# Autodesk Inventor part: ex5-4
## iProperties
Created: 2002-01
Part Number: ex5-4
Document SubType Name: Modeling
Designer: Elise Moss
Density: 1 g/cm^3
Mass: 106.964 g
Surface Area: 328.191 cm^2
Volume: 106.964 cm^3
d0: 4.650 in
d1: 2.325 in
d2: 4.650 in
d3: 2.325 in
d4: 0.200 in
d32: 0.850 in
d33: 0.850 in
d34: 0.168 in
d36: 0.300 in
d37: 0.195 in
d41: 0.030 in
d5: 0.310 in
d6: 0.00 deg
d7: 0.995 in
d8: 0.100 in
d9: 0.00 deg
d12: 0.250 in
d14: 0.675 in
d15: 0.275 in
d19: 0.350 in
d20: 0.350 in
d21: 0.350 in
d22: 0.350 in
d23: 0.168 in
d25: 0.300 in
d26: 0.195 in
d30: 0.850 in
d31: 0.850 in
Author: Elise Moss
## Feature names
1. Extrusion1
2. Extrusion2
3. Hole1
4. Hole2
5. Hole3
6. Fillet1
